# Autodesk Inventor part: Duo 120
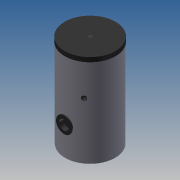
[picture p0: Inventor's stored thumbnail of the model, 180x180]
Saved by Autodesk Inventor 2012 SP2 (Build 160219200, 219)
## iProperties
allow_slope_adjustment: 0 ul
connection_type: 13 ul
flow_configuration2: 1 ul
flow_direction: 2 ul
loss_method: 0 ul
radius: 15,375 mm
radius: 9,500 mm
radius: 16,625 mm
Created: 2014-05
Part Number: Duo 120
Material: Default
Document SubType Name: Modeling
Designer: michel
Density: 1 g/cm^3
radius: 22,625 mm
description: 0:0:18500_Duo_120
manufacturer: 0:0:Flamco Group
model: 0:0:Duo 120
url: 0:0:www.flamcogroup.com
radius: 19,625 mm
Author: michel
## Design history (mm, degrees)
sketch "Sketch1"
  geometry: C1 r 280 at (0, 0); 1 further point
  constraints: 1 centre point, 1 coincident
  dimensions: "d0" = 560 diameter of C1
extrude "Extrusion1" new body sketch "Sketch1" distance "d1" = 1040; taper "d2" = 0 deg
sketch "Sketch2"
  geometry: L1 (-280, 1040)-(280, 1040) reference; L2 (280, 0)-(280, 1040) reference; L3 (280, 1040)-(280, 990); L4 (285, 990)-(285, 1040); L5 (285, 1040)-(280, 1040); L6 (0, -208)-(0, 1248) reference; L7 (285, 990)-(280, 990); 1 further point
  constraints: 8 end point, 1 parallel
revolve "Revolution1" sketch "Sketch2" stored, may be unused: angle "d6" = 90 deg
workplane "Work Plane1"
workplane "Work Plane2"
workplane "Work Plane3"
workplane "Work Plane4"
workplane "Work Plane5"
workplane "Work Plane6"
sketch "Sketch3"
  geometry: L1 (399, 885)-(-399, 885) reference; L2 (399, 635)-(-399, 635) reference; L3 (399, 545)-(-399, 545) reference; L4 (399, 245)-(-399, 245) reference; L5 (399, 65)-(-399, 65) reference; L6 (280, 0)-(280, 990) reference; L7 (290, 885)-(240, 885); L8 (240, 885)-(240, 901.625); L9 (240, 901.625)-(290, 901.625); L10 (290, 901.625)-(290, 885); L11 (290, 65)-(240, 65); L12 (240, 65)-(240, 81.625); L13 (240, 81.625)-(290, 81.625); L14 (290, 81.625)-(290, 65); L15 (280, 635)-(240, 635); L16 (240, 635)-(240, 645.475); L17 (240, 645.475)-(280, 645.475); L18 (280, 645.475)-(280, 635); L19 (280, 545)-(240, 545); L20 (240, 545)-(240, 561.625); L21 (240, 561.625)-(280, 561.625); L22 (280, 561.625)-(280, 545); L23 (240, 261.625)-(280, 261.625); L24 (280, 261.625)-(280, 245); L25 (280, 245)-(240, 245); L26 (240, 245)-(240, 261.625); 1 further point
  constraints: 40 end point, 8 parallel, 4 point on line, 3 horizontal, 3 perpendicular
  dimensions: "d13" = 50 distance of L8.end L9.end; "d14" = 16.625 distance of L7.end L8.end; "d15" = 50 distance of L12.end L13.end; "d16" = 16.625 distance of L11.end L12.end; "d17" = 40 distance of L16.end L17.end; "d18" = 10.475 distance of L15.end L16.end; "d19" = 40 distance of L20.end L21.end; "d20" = 16.625 distance of L19.end L20.end; "d21" = 40 distance of L23.start L23.end; "d22" = 16.625 distance of L25.end L23.start
revolve "Revolution2" stored, may be unused: angle "d23" = 90 deg
revolve "Revolution3" stored, may be unused: angle "d24" = 90 deg
revolve "Revolution4" stored, may be unused: angle "d25" = 90 deg
revolve "Revolution5" stored, may be unused: angle "d26" = 90 deg
revolve "Revolution6" stored, may be unused: angle "d27" = 90 deg
revolve "Revolution7" stored, may be unused: angle "d28" = 90 deg
revolve "Revolution8" stored, may be unused: angle "d29" = 90 deg
sketch "Sketch4"
  geometry: C1 r 16.625 at (0, 0) reference; C2 r 15.375 at (0, 0); 1 further point
  constraints: 1 centre point, 1 coincident
  dimensions: "d30" = 30.75 diameter of C2
extrude "Extrusion2" cut sketch "Sketch4" distance "d31" = 40; taper "d32" = 0 deg
sketch "Sketch5"
  geometry: C1 r 16.625 at (0, 0) reference; C2 r 15.375 at (0, 0); 1 further point
  constraints: 1 centre point, 1 coincident
  dimensions: "d33" = 30.75 diameter of C2
extrude "Extrusion3" cut sketch "Sketch5" distance "d34" = 40; taper "d35" = 0 deg
workplane "Work Plane7"
sketch "Sketch6"
  geometry: C1 r 9.5 at (0, 0); C2 r 16.625 at (0, -90) reference; C3 r 16.625 at (0, -390) reference; C4 r 15.375 at (0, -90); C5 r 15.375 at (0, -390); 7 further points
  constraints: 6 vertical alignment, 3 centre point, 2 coincident
  dimensions: "d36" = 19 diameter of C1; "d37" = 30.75 diameter of C4; "d38" = 30.75 diameter of C5
  node "Projected Loop1"
  node "Projected Loop2"
extrude "Extrusion4" join sketch "Sketch6" distance "d39" = 40; taper "d40" = 0 deg
extrude "Extrusion5" join sketch "Sketch6" distance "d41" = 40; taper "d42" = 0 deg
extrude "Extrusion6" join sketch "Sketch6" distance "d43" = 40; taper "d44" = 0 deg
workplane "Work Plane8"
workplane "Work Plane9"
sketch "Sketch7"
  geometry: L1 (405, 327)-(-400, 327) reference; L2 (-280, 0)-(-280, 990) reference; L3 (-280, 327)-(-292.5, 327); L4 (-292.5, 327)-(-292.5, 417); L5 (-292.5, 417)-(-280, 417); L6 (-280, 417)-(-280, 327); 1 further point
  constraints: 8 end point, 2 parallel, 2 point on line, 1 horizontal, 1 perpendicular
  dimensions: "d47" = 12.5 distance of L4.end L5.end; "d48" = 90 distance of L3.end L4.end
revolve "Revolution9" sketch "Sketch7" stored, may be unused: angle "d49" = 90 deg
sketch "Sketch8"
  geometry: C1 r 62.5 at (0, 0); A1 r 90 centre (0, 0) between (0, -90) and (0, 90) reference; 1 further point
  constraints: 1 centre point, 1 coincident
  dimensions: "d50" = 125 diameter of C1
extrude "Extrusion7" join sketch "Sketch8" stored distance "d51" = 10; taper "d52" = 0 deg
sketch "Sketch9"
  geometry: C1 r 90 at (0, 0) reference; C2 r 55 at (0, 0); 1 further point
  constraints: 1 centre point, 1 coincident
  dimensions: "d53" = 110 diameter of C2
extrude "Extrusion8" cut sketch "Sketch9" distance "d54" = 50; taper "d55" = 0 deg
sketch "Sketch10"
  geometry: C1 r 285 at (0, 0) reference; C2 r 20.955 at (0, 0); C3 r 19.625 at (0, 0)
  constraints: 2 centre point, 2 coincident
  dimensions: "d56" = 41.91 diameter of C2; "d59" = 39.25 diameter of C3
extrude "Extrusion9" cut sketch "Sketch10" distance "d57" = 50; taper "d58" = 0 deg
extrude "Extrusion10" join sketch "Sketch10" distance "d60" = 50; taper "d61" = 0 deg
workplane "Work Plane10"
sketch "Sketch11"
  geometry: L1 (635, -561.842)-(635, 563.89) reference; L2 (0, 280)-(990, 280) reference; L3 (635, 280)-(658.9, 280); L4 (658.9, 280)-(658.9, 240); L5 (658.9, 240)-(635, 240); L6 (635, 240)-(635, 280); L7 (612.375, 240)-(612.375, 280); L8 (612.375, 240)-(609.825, 240); L9 (609.825, 240)-(609.825, 280); L10 (612.375, 280)-(609.825, 280); 1 further point
  constraints: 16 end point, 4 perpendicular, 4 point on line, 2 parallel, 1 horizontal
  dimensions: "d63" = 23.9 distance of L4.end L5.end; "d64" = 40 distance of L3.end L4.end; "d67" = 22.625 distance of L5.end L7.start; "d68" = 2.55 distance of L7.start L8.end
revolve "Revolution10" stored, may be unused: angle "d65" = 90 deg
revolve "Revolution11" stored, may be unused: angle "d69" = 90 deg
body "Solid1"
other parameters: "d7" = -885, "d8" = -65, "d9" = -245, "d10" = -545, "d11" = -635, "d12" = 0, "d45" = -327, "d46" = 0, "d62" = 35 deg
